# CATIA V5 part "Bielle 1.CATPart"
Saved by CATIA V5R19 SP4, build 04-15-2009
Part number: Bielle 1
Publications: "Longueur.1"
Bounding box of the stored display mesh (mm): x -30 to 10, y -19.997 to 19.997, z -20 to 315
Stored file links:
  D:\thinkmotion-MPB\CIAO82010_JCF\PLANTECOSTE\0593\assemblage 593\Bielle 1.CATPart
  D:\thinkmotion-MPB\CIAO82010_JCF\PLANTECOSTE\0593\assemblage 593\593-Plantecoste.CATProduct
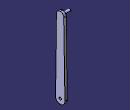
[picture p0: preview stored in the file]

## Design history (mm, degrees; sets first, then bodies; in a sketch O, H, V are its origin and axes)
Parameters
  LENGTH = 300 mm
External parameters (linked from other documents)
  `External.Diamètre axe` = 10 mm
Body1 (main body)
  Sketch1 on yz-plane, origin (0, 0, 0), H (0, 1, 0), V (0, 0, 1)
    construction line L1 (-29.9563, 0) -> (48.0988, 0)
    point P1 (-29.9563, 0)
    point P2 (48.0988, 0)
    line L2 (19.9972, 0.3333) -> (14.9979, 300.25)
    point P3 (14.9979, 300.25)
    arc A1 centre (0, 0) radius 20 from (0, -20) to (19.9972, 0.3333) ccw
    point P4 (0, -20)
    point P5 (19.9972, 0.3333)
    axis line L3 (0, 0) -> (0, 283.3048)
    arc A2 centre (0, 300) radius 15 from (14.9979, 300.25) to (0, 315) ccw
    point P7 (0, 300)
    point P8 (0, 315)
    point P9 (14.9979, 300.25)
    circle A3 centre (0, 0) radius 5
    point P10 (-48.0988, 0)
    point P11 (-14.9979, 300.25)
    point P12 (-19.9972, 0.3333)
    point P13 (-14.9979, 300.25)
    line L4 (-19.9972, 0.3333) -> (-14.9979, 300.25)
    point P14 (0, 315)
    arc A4 centre (0, 300) radius 15 from (-14.9979, 300.25) to (0, 315) cw
    point P16 (0, -20)
    arc A5 centre (0, 0) radius 20 from (0, -20) to (-19.9972, 0.3333) cw
    distance O P7 = 300 {= LENGTH}
    radius A3 = 5 {= `External.Diamètre axe` /2}
    radius A1 = 20 {= `External.Diamètre axe` *2}
    radius A2 = 15 {= `External.Diamètre axe` *1.5}
    coincidence: P1 H, P4 V, P7 L3, P8 L3, P9 P3, P4 P16, P8 P14, P11 P13
    horizontal: L1 H
    tangency: A1 L2, L2 A2
    vertical: L3 V
    symmetry: P2 P10 L3, P3 P11 L3, P5 P12 L3, P9 P13 L3, L2 L4 L3, P8 P14 L3, A2 A4 L3, P4 P16 L3, A1 A5 L3
  Pad1: profile Sketch1, direction (1, 0, 0), length 10 {= LENGTH /30}
  Sketch2 on start face of Pad1, origin (0, 0, 0), H (0, -1, 0), V (0, 0, 1)
    circle A1 centre (0, 300) radius 5
    point P1 (0, 300)
    point P2 (0, 295)
    reference projected arc E1 centre (0, 300) radius 15 from (14.9979, 300.25) to (0, 315) ccw from edge [start face of Pad1 | face of Pad1 from Sketch1.A4]
    radius A1 = 5 {= `External.Diamètre axe` /2}
    coincidence: P1 V, A1 P2, P2 V
    concentricity: A1 E1
  Pad2: profile Sketch2, direction (-1, 0, 0), length 30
